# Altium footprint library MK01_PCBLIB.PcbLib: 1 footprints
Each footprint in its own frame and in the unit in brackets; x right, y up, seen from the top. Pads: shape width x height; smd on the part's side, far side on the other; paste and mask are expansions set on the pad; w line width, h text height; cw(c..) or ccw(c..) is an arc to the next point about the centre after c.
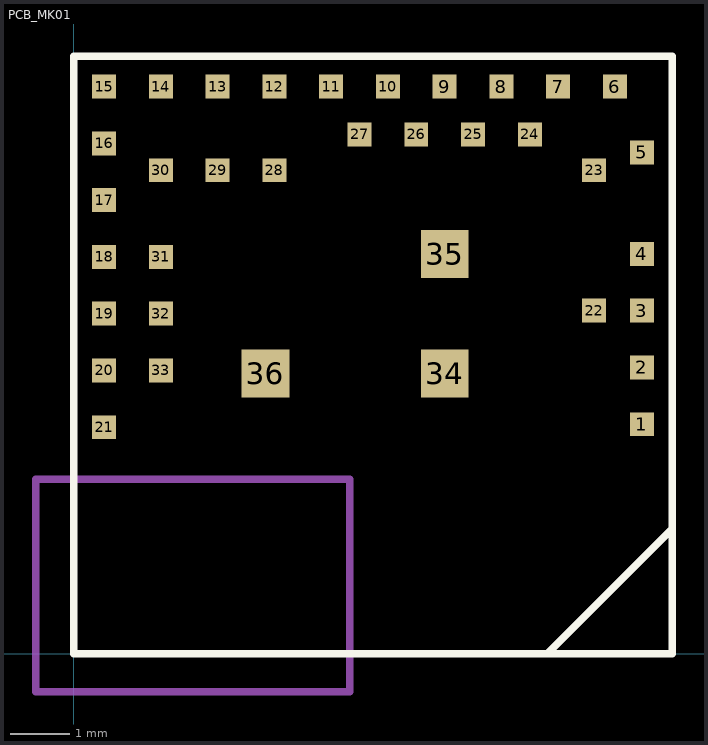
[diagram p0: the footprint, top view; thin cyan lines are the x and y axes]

## PCB_MK01 [mm] "10mm*10mm"
height 2
pads (36):
  rect 0.4x0.4 smd mask+0.102: 1(9.508,3.842) 2(9.508,4.792) 3(9.508,5.742) 4(9.508,6.692) 5(9.508,8.392) 6(9.058,9.492) 7(8.108,9.492) 8(7.158,9.492) 9(6.208,9.492) 10(5.258,9.492) 11(4.308,9.492) 12(3.358,9.492) 13(2.408,9.492) 14(1.458,9.492) 15(0.508,9.492) 16(0.508,8.542) 17(0.508,7.592) 18(0.508,6.642) 19(0.508,5.692) 20(0.508,4.742) 21(0.508,3.792) 22(8.708,5.742) 23(8.708,8.092) 24(7.633,8.692) 25(6.683,8.692) 26(5.733,8.692) 27(4.783,8.692) 28(3.358,8.092) 29(2.408,8.092) 30(1.458,8.092) 31(1.458,6.642) 32(1.458,5.692) 33(1.458,4.742)
  rect 0.8x0.8 smd mask+0.102: 34(6.208,4.692) 35(6.208,6.692) 36(3.208,4.692)
Top Overlay:
  lines w0.127: 7.959,0.032 10.016,2.089 ; 10.016,1.658 10.016,1.683 ; 0,0 0,10 10.016,10 10.016,0 0,0
Mechanical 2:
  lines w0.127: -0.635,-0.635 4.623,-0.635 4.623,2.921 -0.635,2.921 -0.635,-0.635
  text "No ground pad" at 0.432,1.092 h0.3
